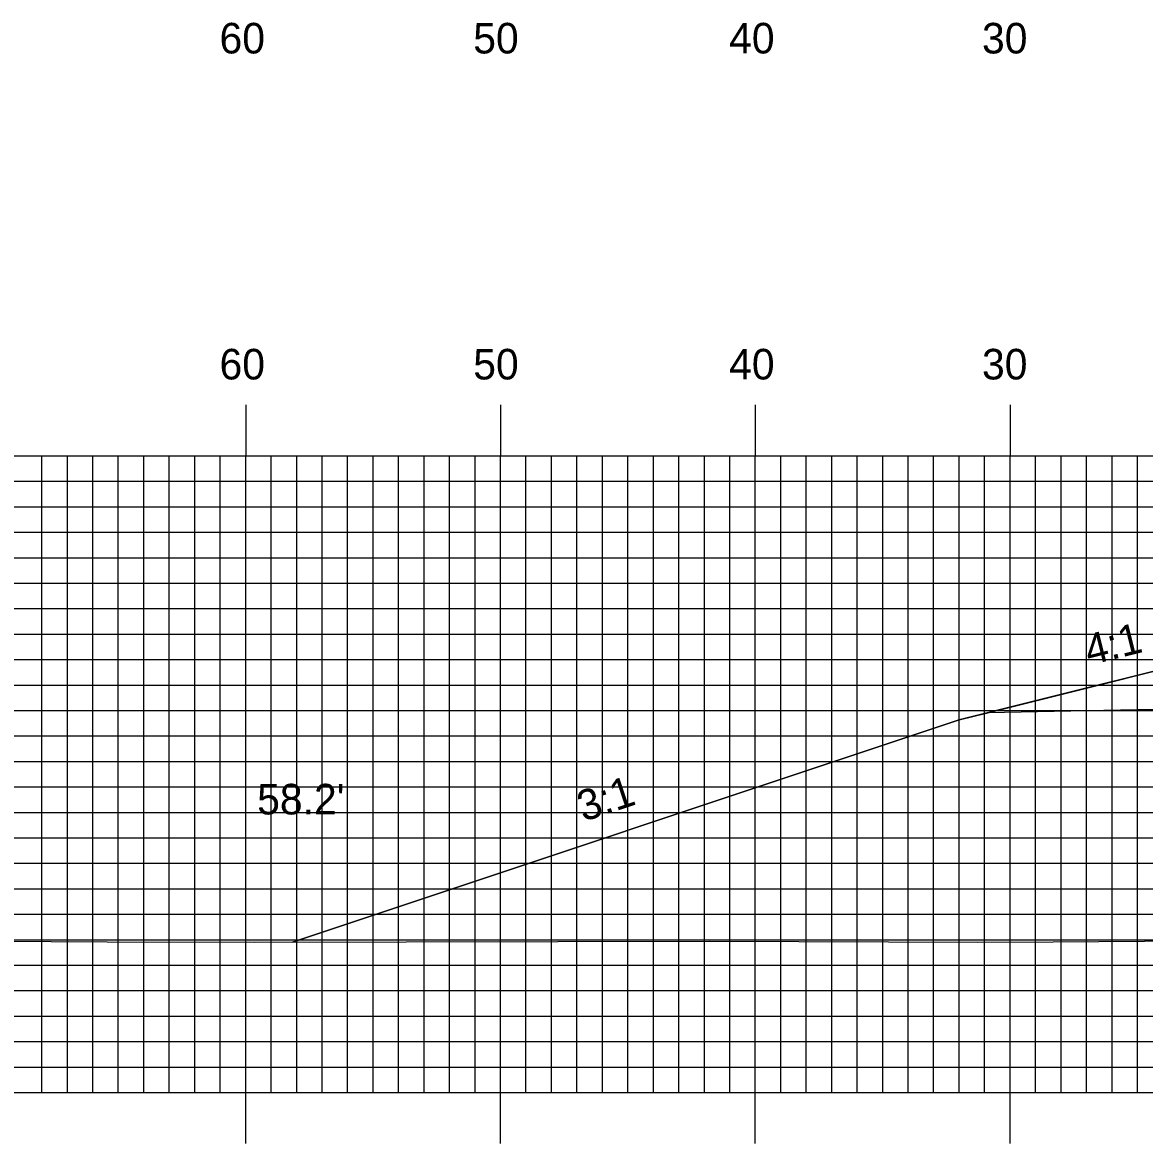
# Model space of a CAD drawing. Extents: x 1814915 to 1815259, y 442591 to 442811.
# Drawn here: x 1815012.26 to 1815056.3, y 442696.66 to 442740.68 of the extents above; entities that cross this region are included whole.
import ezdxf

# ---------------------------------------------------------------- set-up
doc = ezdxf.new("R2010")
doc.units = 0
for name, color, linetype in [('ANNOTATION', 7, 'Continuous'), ('D_Roadway_Centerline', 7, 'Continuous'), ('D_Roadway_SlopeLines', 7, 'Continuous'), ('D_Roadway_SubGrade', 7, 'Continuous'), ('D_Text_Standard', 7, 'Continuous'), ('H_V ANNOTATION', 7, 'Continuous'), ('MAJOR', 7, 'Continuous'), ('MINOR', 7, 'Continuous'), ('S_Roadway_Centerline', 7, 'Continuous')]:
    doc.layers.add(name, color=color, linetype=linetype)

msp = doc.modelspace()

# ---------------------------------------------------------------- linework, layer by layer
at = {"layer": 'D_Roadway_Centerline'}
msp.add_lwpolyline([(1815022.859, 442704.573), (1815049.021, 442713.293), (1815050.151, 442713.576), (1815061.021, 442716.293), (1815069.021, 442716.453), (1815081.021, 442715.877), (1815093.021, 442715.301), (1815101.021, 442714.917), (1815113.021, 442711.917), (1815113.397, 442711.823), (1815134.672, 442704.7)], dxfattribs=at)
at = {"layer": 'D_Roadway_SlopeLines'}
msp.add_lwpolyline([(1815061.021, 442716.293), (1815049.021, 442713.293), (1815022.859, 442704.573)], dxfattribs=at)
at = {"layer": 'D_Roadway_SubGrade'}
msp.add_lwpolyline([(1815069.021, 442713.953), (1815050.151, 442713.576), (1815061.021, 442716.293), (1815061.021, 442716.043), (1815069.021, 442716.203), (1815081.021, 442715.627), (1815093.021, 442715.051), (1815101.021, 442714.667), (1815101.021, 442714.917), (1815113.397, 442711.823), (1815093.021, 442712.801), (1815081.021, 442713.377)], close=True, dxfattribs=at)
at = {"layer": 'MAJOR'}
for p, q in [((1815021.021, 442725.669), (1815021.021, 442723.665)), ((1815031.021, 442725.669), (1815031.021, 442723.665)), ((1815041.021, 442725.669), (1815041.021, 442723.665)), ((1815051.021, 442725.669), (1815051.021, 442723.665)), ((1814941.021, 442723.665), (1815221.021, 442723.665)), ((1814941.021, 442723.665), (1815221.021, 442723.665)), ((1815021.021, 442698.665), (1815021.021, 442723.665)), ((1815031.021, 442698.665), (1815031.021, 442723.665)), ((1815041.021, 442698.665), (1815041.021, 442723.665)), ((1815051.021, 442698.665), (1815051.021, 442723.665)), ((1814941.021, 442718.665), (1815221.021, 442718.665)), ((1814941.021, 442713.665), (1815221.021, 442713.665)), ((1814941.021, 442708.665), (1815221.021, 442708.665)), ((1814941.021, 442703.665), (1815221.021, 442703.665)), ((1814941.021, 442698.665), (1815221.021, 442698.665)), ((1814941.021, 442698.665), (1815221.021, 442698.665)), ((1815021.021, 442696.661), (1815021.021, 442698.665)), ((1815031.021, 442696.661), (1815031.021, 442698.665)), ((1815041.021, 442696.661), (1815041.021, 442698.665)), ((1815051.021, 442696.661), (1815051.021, 442698.665))]:
    msp.add_line(p, q, dxfattribs=at)
at = {"layer": 'MINOR'}
for p, q in [((1815013.021, 442698.665), (1815013.021, 442723.665)), ((1815014.021, 442698.665), (1815014.021, 442723.665)), ((1815015.021, 442698.665), (1815015.021, 442723.665)), ((1815016.021, 442698.665), (1815016.021, 442723.665)), ((1815017.021, 442698.665), (1815017.021, 442723.665)), ((1815018.021, 442698.665), (1815018.021, 442723.665)), ((1815019.021, 442698.665), (1815019.021, 442723.665)), ((1815020.021, 442698.665), (1815020.021, 442723.665)), ((1815022.021, 442698.665), (1815022.021, 442723.665)), ((1815023.021, 442698.665), (1815023.021, 442723.665)), ((1815024.021, 442698.665), (1815024.021, 442723.665)), ((1815025.021, 442698.665), (1815025.021, 442723.665)), ((1815026.021, 442698.665), (1815026.021, 442723.665)), ((1815027.021, 442698.665), (1815027.021, 442723.665)), ((1815028.021, 442698.665), (1815028.021, 442723.665)), ((1815029.021, 442698.665), (1815029.021, 442723.665)), ((1815030.021, 442698.665), (1815030.021, 442723.665)), ((1815032.021, 442698.665), (1815032.021, 442723.665)), ((1815033.021, 442698.665), (1815033.021, 442723.665)), ((1815034.021, 442698.665), (1815034.021, 442723.665)), ((1815035.021, 442698.665), (1815035.021, 442723.665)), ((1815036.021, 442698.665), (1815036.021, 442723.665)), ((1815037.021, 442698.665), (1815037.021, 442723.665)), ((1815038.021, 442698.665), (1815038.021, 442723.665)), ((1815039.021, 442698.665), (1815039.021, 442723.665)), ((1815040.021, 442698.665), (1815040.021, 442723.665)), ((1815042.021, 442698.665), (1815042.021, 442723.665)), ((1815043.021, 442698.665), (1815043.021, 442723.665)), ((1815044.021, 442698.665), (1815044.021, 442723.665)), ((1815045.021, 442698.665), (1815045.021, 442723.665)), ((1815046.021, 442698.665), (1815046.021, 442723.665)), ((1815047.021, 442698.665), (1815047.021, 442723.665)), ((1815048.021, 442698.665), (1815048.021, 442723.665)), ((1815049.021, 442698.665), (1815049.021, 442723.665)), ((1815050.021, 442698.665), (1815050.021, 442723.665)), ((1815052.021, 442698.665), (1815052.021, 442723.665)), ((1815053.021, 442698.665), (1815053.021, 442723.665)), ((1815054.021, 442698.665), (1815054.021, 442723.665)), ((1815055.021, 442698.665), (1815055.021, 442723.665)), ((1815056.021, 442698.665), (1815056.021, 442723.665)), ((1814941.021, 442722.665), (1815221.021, 442722.665)), ((1814941.021, 442721.665), (1815221.021, 442721.665)), ((1814941.021, 442720.665), (1815221.021, 442720.665)), ((1814941.021, 442719.665), (1815221.021, 442719.665)), ((1814941.021, 442717.665), (1815221.021, 442717.665)), ((1814941.021, 442716.665), (1815221.021, 442716.665)), ((1814941.021, 442715.665), (1815221.021, 442715.665)), ((1814941.021, 442714.665), (1815221.021, 442714.665)), ((1814941.021, 442712.665), (1815221.021, 442712.665)), ((1814941.021, 442711.665), (1815221.021, 442711.665)), ((1814941.021, 442710.665), (1815221.021, 442710.665)), ((1814941.021, 442709.665), (1815221.021, 442709.665)), ((1814941.021, 442707.665), (1815221.021, 442707.665)), ((1814941.021, 442706.665), (1815221.021, 442706.665)), ((1814941.021, 442705.665), (1815221.021, 442705.665)), ((1814941.021, 442704.665), (1815221.021, 442704.665)), ((1814941.021, 442702.665), (1815221.021, 442702.665)), ((1814941.021, 442701.665), (1815221.021, 442701.665)), ((1814941.021, 442700.665), (1815221.021, 442700.665)), ((1814941.021, 442699.665), (1815221.021, 442699.665))]:
    msp.add_line(p, q, dxfattribs=at)
at = {"layer": 'S_Roadway_Centerline'}
msp.add_lwpolyline([(1815000.169, 442704.68), (1815015.578, 442704.582), (1815021.368, 442704.57), (1815039.224, 442704.611), (1815049.751, 442704.571), (1815052.709, 442704.58), (1815067.032, 442704.683), (1815067.761, 442704.681), (1815068.351, 442704.676), (1815082.894, 442704.567), (1815088.232, 442704.582), (1815100.175, 442704.641), (1815108.045, 442704.671), (1815117.207, 442704.639), (1815131.781, 442704.692), (1815133.513, 442704.676), (1815134.615, 442704.7), (1815138.795, 442704.685)], dxfattribs=at)

# ---------------------------------------------------------------- texts
at = {"layer": 'ANNOTATION'}
for s, rotation, p in [('4:1', 14.0362, (1815054.121, 442715.43)), ('3:1', 18.4348, (1815034.279, 442709.288))]:
    msp.add_text(s, height=1.2, rotation=rotation, dxfattribs=at).set_placement(p)
at = {"layer": 'D_Text_Standard'}
msp.add_text("58.2'", height=1.2, dxfattribs=at).set_placement((1815021.47, 442709.585))
at = {"layer": 'H_V ANNOTATION'}
for s, p in [('60', (1815019.993, 442739.465)), ('50', (1815029.95, 442739.465)), ('40', (1815039.993, 442739.465)), ('30', (1815049.918, 442739.465)), ('60', (1815019.993, 442726.665)), ('50', (1815029.95, 442726.665)), ('40', (1815039.993, 442726.665)), ('30', (1815049.918, 442726.665))]:
    msp.add_text(s, height=1.2, dxfattribs=at).set_placement(p)

doc.saveas('drawing.dxf')
